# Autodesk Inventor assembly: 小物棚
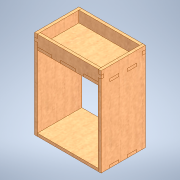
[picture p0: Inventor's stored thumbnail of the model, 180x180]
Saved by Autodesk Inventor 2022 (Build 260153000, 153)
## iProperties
Created: 2024-11
Part Number: 小物棚
Document SubType Name: Assembly
Designer: shimizu
Mass: 23.8 g
Surface Area: 271.6 cm^2
Volume: 29.75 cm^3
Density: 0.8 g/cm^3
Author: shimizu
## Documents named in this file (5)
- C:\Users\shimizu\Documents\卒論2024\3DCAD\小物棚\組立図\小物棚.iam
- C:\Users\shimizu\Documents\卒論2024\3DCAD\小物棚\部品図\底板.ipt
- C:\Users\shimizu\Documents\卒論2024\3DCAD\小物棚\部品図\側板.ipt
- C:\Users\shimizu\Documents\卒論2024\3DCAD\小物棚\部品図\天板.ipt
- C:\Users\shimizu\Documents\卒論2024\3DCAD\小物棚\部品図\側板②.ipt
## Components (6 placed, 4 different names)
1. 底板:1 — メイト:1, メイト:2, フラッシュ:1, メイト:3, フラッシュ:2, フラッシュ:3
2. 側板:1 — メイト:1, メイト:2, フラッシュ:1, フラッシュ:4, フラッシュ:6, フラッシュ:7, フラッシュ:10
3. 側板:2 — メイト:3, フラッシュ:2, フラッシュ:3, フラッシュ:5, メイト:4, フラッシュ:8, フラッシュ:9, メイト:5
4. 天板:1 — フラッシュ:4, フラッシュ:5, メイト:4
5. 側板②:1 — フラッシュ:6, フラッシュ:7, フラッシュ:8
6. 側板②:2 — フラッシュ:9, フラッシュ:10, メイト:5
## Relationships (15: Flush 10, Mate 5)
- メイト:1 [Mate]: 底板:1 ↔ 側板:1
- メイト:2 [Mate]: 底板:1 ↔ 側板:1
- フラッシュ:1 [Flush]: 底板:1 ↔ 側板:1
- メイト:3 [Mate]: 底板:1 ↔ 側板:2
- フラッシュ:2 [Flush]: 底板:1 ↔ 側板:2
- フラッシュ:3 [Flush]: 底板:1 ↔ 側板:2
- フラッシュ:4 [Flush]: 側板:1 ↔ 天板:1
- フラッシュ:5 [Flush]: 側板:2 ↔ 天板:1
- メイト:4 [Mate]: 側板:2 ↔ 天板:1
- フラッシュ:6 [Flush]: 側板:1 ↔ 側板②:1
- フラッシュ:7 [Flush]: 側板:1 ↔ 側板②:1
- フラッシュ:8 [Flush]: 側板:2 ↔ 側板②:1
- フラッシュ:9 [Flush]: 側板:2 ↔ 側板②:2
- フラッシュ:10 [Flush]: 側板:1 ↔ 側板②:2
- メイト:5 [Mate]: 側板:2 ↔ 側板②:2
## Named parameters: sa_0 = 50000 mm
